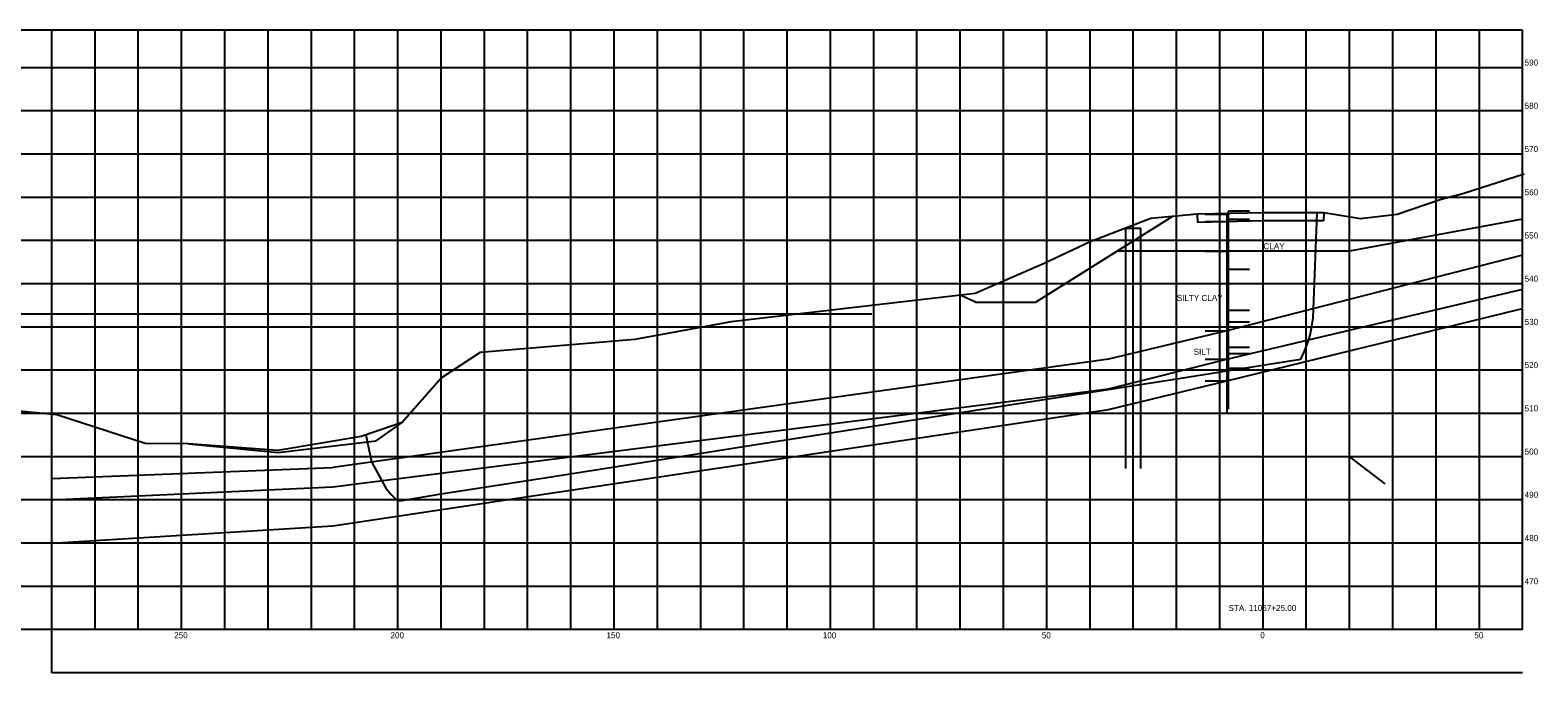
# Model space of a CAD drawing. Extents: x -64 to 1064, y -32 to 640.
# Drawn here: x 715 to 1063.5, y 225.9 to 374.6 of the extents above; entities that cross this region are included whole.
import ezdxf

# ---------------------------------------------------------------- set-up
doc = ezdxf.new("R2010")
doc.units = 0
for name, color, linetype in [('DR_X_Headwall', 7, 'Continuous'), ('GT_Project_Soil_Boring', 7, 'Continuous'), ('GT_Project_Soil_Layers', 7, 'Continuous'), ('GT_X_Shear_Surface', 7, 'Continuous'), ('SC_Scratch1', 7, 'Continuous'), ('SH_Major_Grid_Line', 7, 'Continuous'), ('SH_Text', 7, 'Continuous')]:
    doc.layers.add(name, color=color, linetype=linetype)

msp = doc.modelspace()

# ---------------------------------------------------------------- linework, layer by layer
at = {"layer": 'DR_X_Headwall'}
for p, q in [((968.25, 328.78), (971.75, 328.78)), ((968.25, 273.19), (968.25, 328.78)), ((971.75, 273.19), (971.75, 328.78))]:
    msp.add_line(p, q, dxfattribs=at)
at = {"layer": 'GT_Project_Soil_Boring'}
for p, q in [((986.6, 331.98), (991.6, 331.98)), ((991.6, 331.98), (991.6, 286.21)), ((991.9, 332.68), (991.9, 286.88)), ((996.9, 332.68), (991.9, 332.68)), ((986.6, 330.28), (991.6, 330.28)), ((996.9, 330.78), (991.9, 330.78)), ((986.6, 323.48), (991.6, 323.48)), ((996.9, 319.18), (991.9, 319.18)), ((996.9, 309.68), (991.9, 309.68)), ((996.9, 306.98), (991.9, 306.98)), ((986.6, 304.98), (991.6, 304.98)), ((996.9, 301.18), (991.9, 301.18)), ((986.6, 298.48), (991.6, 298.48)), ((996.9, 299.68), (991.9, 299.68))]:
    msp.add_line(p, q, dxfattribs=at)
at = {"layer": 'GT_Project_Soil_Layers'}
for p, q in [((979.05, 331.47), (947.47, 311.66)), ((984.75, 331.98), (984.85, 330.08)), ((1014.08, 332.34), (1013.98, 330.44)), ((933.5, 311.66), (930, 313.27)), ((933.5, 311.66), (947.47, 311.66)), ((996.9, 296.28), (991.9, 296.28)), ((986.6, 293.48), (991.6, 293.48)), ((720, 270.88), (785, 273.38)), ((720, 265.88), (785, 268.88)), ((720, 255.88), (785, 259.88))]:
    msp.add_line(p, q, dxfattribs=at)
for points in [[(1014.08, 332.34), (1000, 332.33), (984.75, 331.98)], [(1060, 330.88), (1020, 323.48), (966.31, 323.48)], [(1013.98, 330.44), (1000, 330.43), (984.85, 330.08)], [(1060, 322.49), (991.6, 304.98), (964.25, 298.45), (785, 273.38)], [(785, 268.88), (964.25, 291.63), (991.6, 298.48), (1059.7, 314.56)], [(785, 259.88), (964.25, 286.78), (991.6, 293.48), (1059.7, 310.12)]]:
    msp.add_lwpolyline(points, dxfattribs=at)
at = {"layer": 'GT_X_Shear_Surface'}
msp.add_lwpolyline([(792.6, 280.98), (793.9, 274.68), (797.2, 268.58), (798.5, 267.08), (799.9, 265.68), (801, 265.78), (810, 267.28), (834.4, 271.08), (860.4, 275.18), (887.2, 279.38), (933.5, 286.68), (979.1, 293.78), (991.6, 295.78), (1004.3, 297.78), (1008.7, 298.48), (1009.6, 300.28), (1010.3, 302.08), (1010.6, 302.98), (1010.9, 303.98), (1011.3, 305.98), (1011.6, 307.98), (1011.7, 309.98), (1012.51, 332.34)], dxfattribs=at)
at = {"layer": 'SC_Scratch1'}
for p, q in [((909.57, 308.88), (628.77, 308.88)), ((1020, 275.88), (1028.17, 269.62))]:
    msp.add_line(p, q, dxfattribs=at)
for points in [[(1060.34, 341.22), (1046.19, 336.74), (1041.14, 335.38), (1031.04, 331.96), (1022.54, 330.96), (1014.08, 332.34), (1000.1, 332.33), (984.75, 331.98), (974.05, 331.02), (960.03, 325.62), (949.37, 320.59), (933.45, 313.64), (877.04, 307.11), (854.76, 303), (819.06, 299.98), (810.1, 294.16), (801.03, 283.83), (791.54, 280.56), (772.26, 277.32), (751.61, 278.88), (741.55, 278.95), (721.15, 285.54), (710.8, 286.6)], [(751.61, 278.88), (772.3, 276.88), (795, 279.58), (801.03, 283.83)]]:
    msp.add_lwpolyline(points, dxfattribs=at)
at = {"layer": 'SH_Major_Grid_Line'}
for p, q in [((1060, 374.58), (660, 374.58)), ((720, 225.88), (720, 374.58)), ((730, 235.88), (730, 374.58)), ((740, 235.88), (740, 374.58)), ((750, 235.88), (750, 374.58)), ((760, 235.88), (760, 374.58)), ((770, 235.88), (770, 374.58)), ((780, 235.88), (780, 374.58)), ((790, 235.88), (790, 374.58)), ((800, 235.88), (800, 374.58)), ((810, 235.88), (810, 374.58)), ((820, 235.88), (820, 374.58)), ((830, 235.88), (830, 374.58)), ((840, 235.88), (840, 374.58)), ((850, 235.88), (850, 374.58)), ((860, 235.88), (860, 374.58)), ((870, 235.88), (870, 374.58)), ((880, 235.88), (880, 374.58)), ((890, 235.88), (890, 374.58)), ((900, 235.88), (900, 374.58)), ((910, 235.88), (910, 374.58)), ((920, 235.88), (920, 374.58)), ((930, 235.88), (930, 374.58)), ((940, 235.88), (940, 374.58)), ((950, 235.88), (950, 374.58)), ((960, 235.88), (960, 374.58)), ((970, 235.88), (970, 374.58)), ((980, 235.88), (980, 374.58)), ((990, 235.88), (990, 374.58)), ((1000, 235.88), (1000, 374.58)), ((1010, 235.88), (1010, 374.58)), ((1020, 235.88), (1020, 374.58)), ((1030, 235.88), (1030, 374.58)), ((1040, 235.88), (1040, 374.58)), ((1050, 235.88), (1050, 374.58)), ((1060, 235.88), (1060, 374.58)), ((1060, 365.88), (660, 365.88)), ((1060, 355.88), (660, 355.88)), ((1060, 345.88), (660, 345.88)), ((1060, 335.88), (660, 335.88)), ((1060, 325.88), (660, 325.88)), ((1060, 315.88), (660, 315.88)), ((1060, 305.88), (660, 305.88)), ((1060, 295.88), (660, 295.88)), ((1060, 285.88), (660, 285.88)), ((1060, 275.88), (660, 275.88)), ((1060, 265.88), (660, 265.88)), ((1060, 255.88), (660, 255.88)), ((1060, 245.88), (660, 245.88)), ((1060, 235.88), (660, 235.88)), ((1060, 225.88), (720, 225.88))]:
    msp.add_line(p, q, dxfattribs=at)

# ---------------------------------------------------------------- texts
at = {"layer": 'GT_Project_Soil_Boring'}
for s, p in [('CLAY', (1000.1, 323.9)), ('SILTY CLAY', (980.06, 311.93)), ('SILT', (983.96, 299.49))]:
    msp.add_text(s, height=1.4, dxfattribs=at).set_placement(p)
at = {"layer": 'SH_Text'}
for s, p in [('590', (1060.47, 366.38)), ('580', (1060.47, 356.38)), ('570', (1060.47, 346.38)), ('560', (1060.47, 336.38)), ('550', (1060.47, 326.38)), ('540', (1060.47, 316.38)), ('530', (1060.47, 306.38)), ('520', (1060.47, 296.38)), ('510', (1060.47, 286.38)), ('500', (1060.47, 276.38)), ('490', (1060.48, 266.38)), ('480', (1060.48, 256.38)), ('470', (1060.48, 246.38)), ('STA. 11067+25.00', (992.03, 240.18)), ('250', (748.29, 233.88)), ('200', (798.29, 233.88)), ('150', (848.22, 233.88)), ('100', (898.22, 233.88)), ('50', (948.85, 233.88)), ('0', (999.36, 233.88)), ('50', (1048.85, 233.88))]:
    msp.add_text(s, height=1.4, dxfattribs=at).set_placement(p)

doc.saveas('drawing.dxf')
